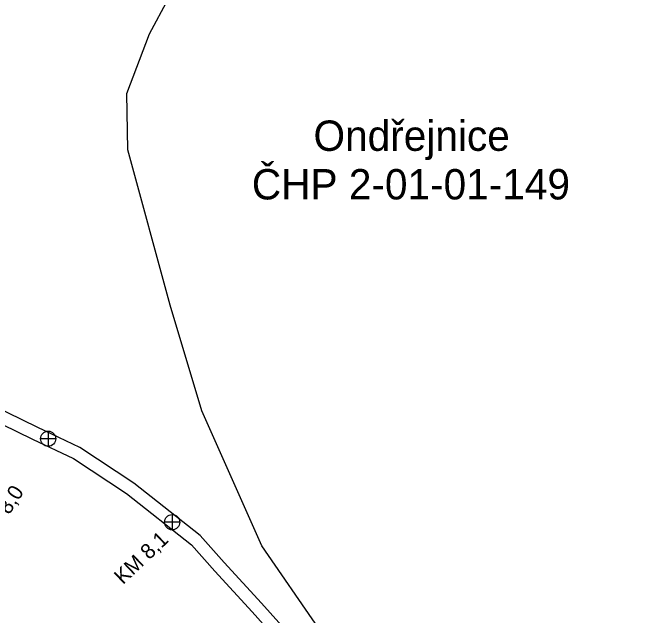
# Model space of a CAD drawing. Extents: x -478232 to -472707, y -1118753 to -1113967.
# Drawn here: x -476364.6 to -475947.8, y -1116313.9 to -1115916.9 of the extents above; entities that cross this region are included whole.
import ezdxf

# ---------------------------------------------------------------- set-up
doc = ezdxf.new("R2010")
doc.units = 0
for name, color, linetype in [('povodí', 7, 'Continuous'), ('silnice', 7, 'Continuous'), ('staničení toku', 7, 'Continuous'), ('vodní plochy', 7, 'Continuous')]:
    doc.layers.add(name, color=color, linetype=linetype)

msp = doc.modelspace()

# ---------------------------------------------------------------- linework, layer by layer
at = {"layer": 'silnice'}
msp.add_lwpolyline([(-475903.982, -1117378.322), (-475889.519, -1117318.176), (-475888.389, -1117289.008), (-475895.395, -1117261.196), (-475916.638, -1117209.19), (-475969.886, -1117075.455), (-476021.05, -1116948.737), (-476052.923, -1116863.979), (-476081.44, -1116727.192), (-476114.99, -1116491.378), (-476128.411, -1116405.781), (-476137.637, -1116368.017), (-476162.8, -1116322.7), (-476200.543, -1116268.153), (-476239.965, -1116179.199), (-476260.934, -1116109.546), (-476288.613, -1116007.164), (-476289.451, -1115970.24), (-476274.354, -1115930.798), (-476261.922, -1115907.288), (-476366.595, -1115823.727)], dxfattribs=at)
at = {"layer": 'staničení toku'}
for p, q in [((-476341.214, -1116192.579), (-476341.214, -1116202.579)), ((-476336.214, -1116197.579), (-476346.214, -1116197.579)), ((-476259.519, -1116247.607), (-476259.519, -1116257.607)), ((-476254.519, -1116252.607), (-476264.519, -1116252.607))]:
    msp.add_line(p, q, dxfattribs=at)
for centre in [(-476341.214, -1116197.579), (-476259.519, -1116252.607)]:
    msp.add_circle(centre, 5, dxfattribs=at)
at = {"layer": 'vodní plochy'}
for points in [[(-476181.445, -1116327.327), (-476200.558, -1116305.872), (-476225.178, -1116279.205), (-476240.993, -1116261.287), (-476284.697, -1116226.903), (-476320.29, -1116203.316), (-476347.924, -1116190.183), (-476388.083, -1116170.718)], [(-476391.698, -1116178.366), (-476351.584, -1116197.809), (-476324.463, -1116210.698), (-476289.656, -1116233.764), (-476246.827, -1116267.46), (-476231.457, -1116284.873), (-476206.824, -1116311.554), (-476188.29, -1116332.359)]]:
    msp.add_lwpolyline(points, dxfattribs=at)

# ---------------------------------------------------------------- texts
at = {"layer": 'povodí'}
for s, p in [('Ondřejnice', (-476166.394, -1116007.946)), ('ČHP 2-01-01-149', (-476207.017, -1116039.946))]:
    msp.add_text(s, height=20, rotation=359.99999, dxfattribs=at).set_placement(p)
at = {"layer": 'staničení toku'}
for s, rotation, p in [('KM 8,0', 56.8195, (-476379.958, -1116268.01)), ('KM 8,1', 43.47786, (-476291.939, -1116294.118))]:
    msp.add_text(s, height=10, rotation=rotation, dxfattribs=at).set_placement(p)

doc.saveas('drawing.dxf')
